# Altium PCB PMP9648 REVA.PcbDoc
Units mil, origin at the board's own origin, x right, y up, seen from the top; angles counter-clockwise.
Board outline 3200 x 1500 mil, 2 copper layers (Top Layer, Bottom Layer), stack 64.8 mil thick; 58 components, 29 nets, 134 pads, 77 vias.
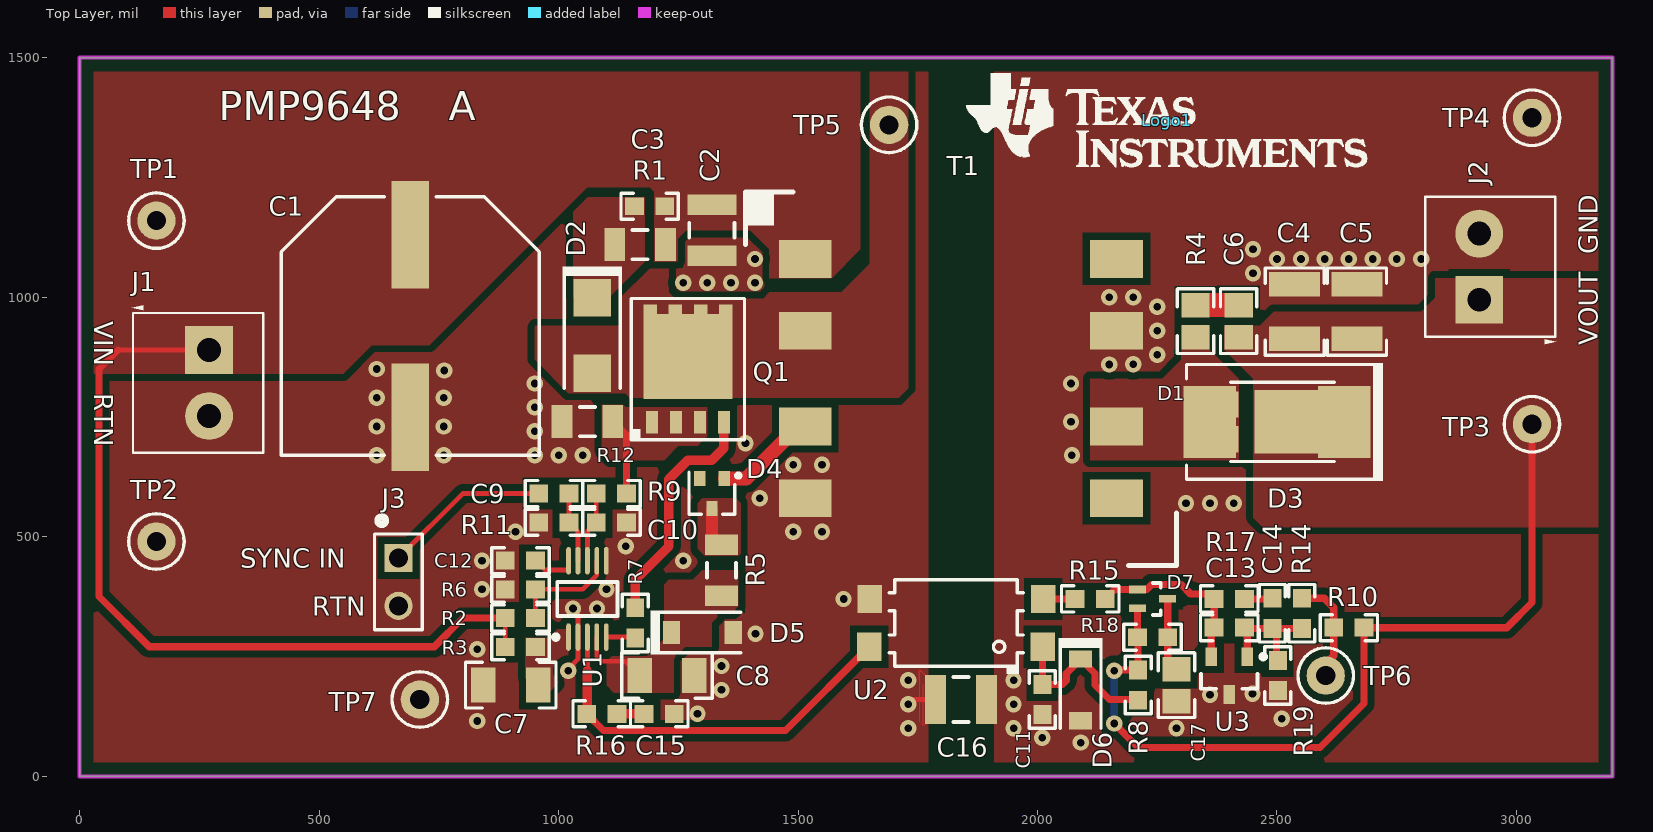
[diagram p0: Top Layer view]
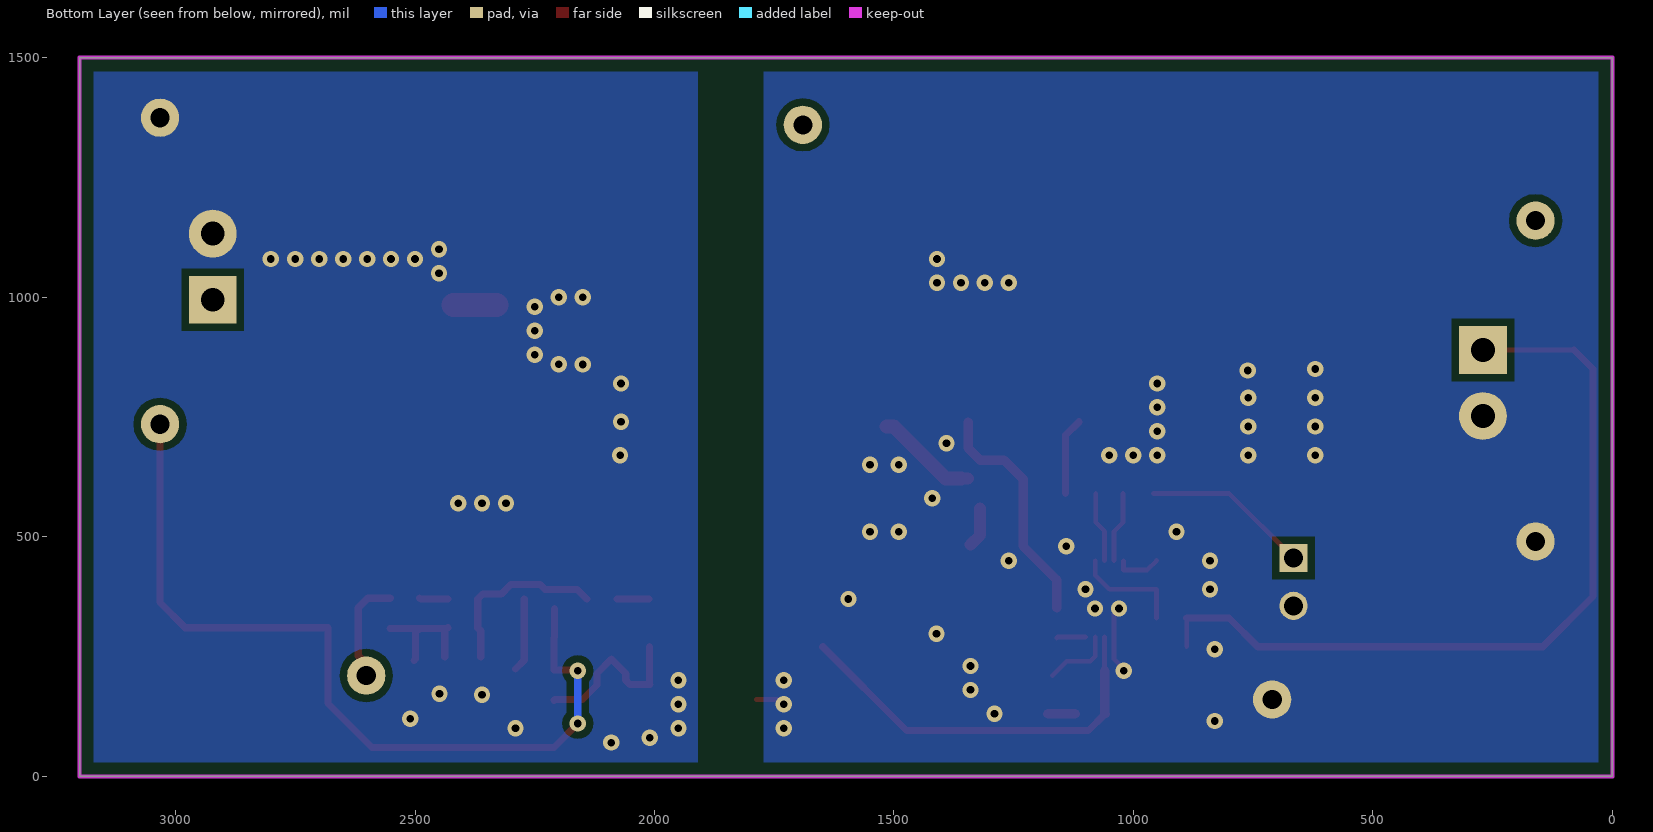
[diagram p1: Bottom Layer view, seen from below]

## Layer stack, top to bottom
Top Solder: solder mask 0.4, Solder Resist, Dk 3.5
Top Layer: signal copper 2.8
Dielectric1: core 59.2, FR-4, Dk 4.8
Bottom Layer: signal copper 2.8
Bottom Solder: solder mask 0.4, Solder Resist, Dk 3.5

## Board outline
0,0 3200,0 3200,1500 0,1500

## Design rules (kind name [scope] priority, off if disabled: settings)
AcuteAngle [All] p1: minimum=4.50000000000000E+0001 checktracksonly=FALSE
AssemblyTestPointUsage [All] p1: valid=2
Clearance Clearance_BoardEdge_MountingHoles [OnCopper and InComponentClass('Mounting Holes') vs IsKeepOut] p1: gap=25
Clearance Clearance_BoardEdge_Poly [OnCopper and InPoly vs IsKeepOut] p2: gap=25
Clearance Clearance_BoardEdge [OnCopper and Not InComponentClass('Logo') and not InComponentClass('FiducialMark') and not InRegion(1000,500,4000,800) and Not IsKeepout vs IsKeepOut] p3: gap=25
Clearance Clearance_Poly [InPolygon] p4: gap=15
Clearance [All] p5: gap=8
ComponentClearance ComponentClearance_Shunt [InComponentClass('Header') vs InComponentClass('Shunt')] p1: gap=0 collisioncheckmode=3 verticalgap=0 showdistances=FALSE
ComponentClearance ComponentClearance_Logo [InComponentClass('Logo')] p2: gap=50 collisioncheckmode=3 verticalgap=10 showdistances=FALSE
ComponentClearance ComponentClearance_ScrewToNut [(HasFootprint('NY PMS 440 0025 PH')) vs (HasFootprint('Keystone_1902C'))] p3: gap=5 collisioncheckmode=3 verticalgap=10 showdistances=FALSE
ComponentClearance ComponentClearance_MountingHoles [InComponentClass('Mounting Holes')] p4: gap=250 collisioncheckmode=3 verticalgap=100000 showdistances=FALSE
ComponentClearance ComponentClearance_SmallPassives [HasFootprint('0201*') or HasFootprint('0402*') or HasFootprint('0508') or HasFootprint('0603*') or HasFootprint('0612') or HasFootprint('0805*') or HasFootprint('0815*') or HasFootprint('0830*') or HasFootprint('1206*') or HasFootprint('1210*') or HasFootprint('1808*') or HasFootprint('1812*') or HasFootprint('1825*') or HasFootprint('2010*') or HasFootprint('2220*') or HasFootprint('2225*') or HasFootprint('2512*') or HasFootprint('2728*') or HasFootprint('3518*') vs HasFootprint('0201*') or HasFootprint('0402*') or HasFootprint('0508') or HasFootprint('0603*') or HasFootprint('0612') or HasFootprint('0805*') or HasFootprint('0815*') or HasFootprint('0830*') or HasFootprint('1206*') or HasFootprint('1210*') or HasFootprint('1808*') or HasFootprint('1812*') or HasFootprint('1825*') or HasFootprint('2010*') or HasFootprint('2220*') or HasFootprint('2225*') or HasFootprint('2512*') or HasFootprint('2728*') or HasFootprint('3518*')] p5: gap=10 collisioncheckmode=3 verticalgap=10 showdistances=FALSE
ComponentClearance ComponentClearance_THtoSMT [IsThruComponent vs IsSMTComponent] p6: gap=20 collisioncheckmode=3 verticalgap=30 showdistances=FALSE
ComponentClearance ComponentClearance_THtoTH [IsThruComponent vs IsThruComponent] p7: gap=50 collisioncheckmode=3 verticalgap=30 showdistances=FALSE
ComponentClearance [All] p8: gap=15 collisioncheckmode=3 verticalgap=10 showdistances=FALSE
DiffPairsRouting [All] p1: maxlimit=100 minlimit=10 mostfreqgap=10 toplayer_minwidth=15 toplayer_maxwidth=15 toplayer_prefwidth=15 bottomlayer_minwidth=15 bottomlayer_maxwidth=15 bottomlayer_prefwidth=15 maxuncoupledlength=1000
FabricationTestPointUsage TestPointUsage [All] p1: valid=2 allowmultiple=FALSE
FabricationTestpoint Testpoint [All] p1: side=3 testpointundercomponent=TRUE minsize=40 maxsize=100 preferedsize=60 minholesize=0 maxholesize=40 preferedholesize=32 testpointgrid=1 allowsidetop=TRUE allowsidebottom=TRUE usegrid=TRUE gridtolerance=0.01
FanoutControl Fanout_LCC [IsLCC] p1: bgadir=Out bgaviamode=Centered fanoutstyle=Auto fanoutdirection=Alternating viagrid=1 // Fanout_LCC (Default Rule)
FanoutControl Fanout_BGA [IsBGA] p2: bgadir=Out bgaviamode=Centered fanoutstyle=Auto fanoutdirection=Alternating viagrid=1 // Fanout_BGA (Default Rule)
FanoutControl Fanout_Default [All] p4: bgadir=Out bgaviamode=Centered fanoutstyle=Auto fanoutdirection=Alternating viagrid=1 // Fanout_Default (Default Rule)
FanoutControl Fanout_Small [(CompPinCount < 5)] p5: bgadir=Out bgaviamode=Centered fanoutstyle=Auto fanoutdirection=OutThenIn viagrid=1 // Fanout_Small (Default Rule)
HoleSize [All] p1: absolutevalues=TRUE maxlimit=251 minlimit=8 maxpercent=80.000 minpercent=20.000
MinimumAnnularRing MinimumAnnularRing_ThermalPadVias [IsVia and InAnyComponent] p1: minimumring=5.91
MinimumAnnularRing [All] p2: minimumring=9
MinimumSolderMaskSliver MinimumSolderMaskSliver_Logo [InComponentClass('Logo') vs InComponentClass('Logo')] p1: minsoldermaskwidth=0.7
MinimumSolderMaskSliver [All] p2: minsoldermaskwidth=3.94
PlaneClearance [All] p1: clearance=10
PlaneConnect [All] p1: planeconnectstyle=Direct reliefexpansion=10 reliefentries=4 reliefconductorwidth=10 reliefairgap=10
PolygonConnect [All] p1: connectstyle=Direct reliefconductorwidth=10 reliefentries=4 polygonreliefangle="90 Angle" airgapwidth=10
RoutingVias ThermalPadVias [IsVia and InAnyComponent] p1: holewidth=7.87 width=19.68 viastyle="Through Hole" minholewidth=7.87 minwidth=19.68 maxholewidth=12.99 maxwidth=23.62
RoutingVias [All] p2: holewidth=16 width=34 viastyle="Through Hole" minholewidth=7.87 minwidth=26 maxholewidth=40 maxwidth=65
SMDToCorner [All] p1: distance=30000
SilkToSilkClearance [All] p1: silktosilkclearance=0
SilkToSolderMaskClearance SilkscreenOverComponentPads [IsPad] p1: minsilkscreentomaskgap=0 clearancetoexposedcopper=TRUE
SolderMaskExpansion [All] p1: expansion=1.97
Width [All] p1: maxlimit=100 minlimit=6 preferedwidth=10 checkconnectedcopper=TRUE
15 further rules are at their usual default settings.

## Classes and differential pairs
component class Logo: Logo1

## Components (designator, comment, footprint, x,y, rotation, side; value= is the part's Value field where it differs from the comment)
C1 "EEV-FK2A470Q" SM_RADIAL_H13 690,940 r270 top
C2 "C3225X7R2A225M230AB" 1210L 1320,1140 r270 top
C3 "GRM188R72A104KA35D" 0603 1190,1190 r180 top
C4 "C3225X7R1C226M250AC" 1210 2536.85,970 r90 top
C5 "C3225X7R1C226M250AC" 1210 2666.85,970 r90 top
C6 "GRM2165C2A331JA01D" 0805 2420,950 r90 top
C7 "C3216X7R2A105M160AA" 1206 900,190 r180 top
C8 "C3216X7R1C106M" 1206 1226.5,210 r0 top
C9 "C1608C0G1H101J" 0603 990,590 r0 top
C10 "C1608C0G1H101J" 0603 1110,530 r180 top
C11 "DNP" 0603 2010,160 r270 top
C12 "C1608X7R1H103K" 0603 920,450 r180 top
C13 "" 0603 2400.31,310 r0 top
C14 "C1608X7R2A472K" 0603 2490.31,340 r270 top
C15 "GRM188R72A104KA35D" 0603 1210,130 r180 top
C16 "C1210C102KGRACTU" 1210L 1840,160 r180 top
C17 "GRM21BR61E225KA12L" 0805 2290.31,190 r270 top
D1 "DNP" PowerDI5 2470,739.68 r0 top
D2 "MURA120T3G" SMA 1070,920 r270 top
D3 "B560C-13-F" SMC 2500,739.68 r180 top
D4 "BAV21WS-7-F" SOT-323 1320,590 r270 top
D5 "MMSZ4699T1G" SOD-123 1300,300 r0 top
D6 "DNP" SOD-123 2090,180 r270 top
D7 "BAT54ST-7-F" SOT-523 2240.31,370 r0 top
J1 "ED555/2DS" TERM_BLK_ED555-2DS 270,890 r270 top
J2 "ED555/2DS" TERM_BLK_ED555-2DS 2922.35,994.8 r90 top
J3 "PEC02SAAN" CONN_PEC02SAAN 665.47,405.47 r270 top
Logo1 "Texas Instruments" TI_Stacked_Overlay_Small 2270,1370 r0 top
Q1 "BSC12DN20NS3 G" PG-TDSON-8 1270,850 r90 top
R1 "CRCW120649K9FKEA" 1206L 1170,1110 r0 top
R2 "CRCW0603100KFKEA" 0603 920,330 r180 top
R3 "CRCW06033R24FKEA" 0603 920,270 r180 top
R4 "CRCW080522R1FKEA" 0805 2330,950 r90 top
R5 "CRCW120620R0JNEA" 1206L 1340,430 r270 top
R6 "CRCW06033K74FKEA" 0603 920,390 r0 top
R7 "MCR03EZPJ000" 0603 1160,320 r90 top
R8 "CRCW06034K64FKEA" 0603 2210,190 r270 top
R9 "CRCW0603221RFKEA" 0603 1110,590 r0 top
R10 "CRCW06030000Z0EA" 0603 2650,310 r0 top
R11 "CRCW060342K2FKEA" 0603 990,530 r0 top
R12 "RLP73K2BR16FTDF" 1206L 1060,740 r0 top
R14 "CRCW0603100KFKEA" 0603 2551.81,340 r90 top
R15 "CRCW06031K50FKEA" 0603 2110,370 r180 top
R16 "CRCW06031K15FKEA" 0603 1090,130 r180 top
R17 "CRCW0603100KFKEA" 0603 2400.31,370 r180 top
R18 "CRCW060310K0FKEA" 0603 2240.31,290 r180 top
R19 "CRCW060311K3FKEA" 0603 2501.81,210 r90 top
T1 "750314749" RENCO_RLTI-1102 1840,830 r270 top
TP1 "5000" Keystone5000 160,1160 r0 top
TP2 "5001" Keystone5001 160,490 r0 top
TP3 "5000" Keystone5000 3032.35,734.8 r0 top
TP4 "5001" Keystone5001 3032.35,1374.8 r0 top
TP5 "5000" Keystone5000 1690,1360 r0 top
TP6 "5000" Keystone5000 2601.81,210 r0 top
TP7 "5001" Keystone5001 710,160 r0 top
U1 "LM5022MM" MUB10A_L 1060,370 r90 top
U2 "FOD817AS" N04C 1830,320 r180 top
U3 "LMV431AIMFX/NOPB" MF03A_L 2400.31,210 r270 top

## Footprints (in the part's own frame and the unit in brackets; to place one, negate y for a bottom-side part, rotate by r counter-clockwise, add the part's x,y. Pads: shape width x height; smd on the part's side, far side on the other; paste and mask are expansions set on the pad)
0603 [mm] "0603 from SM-752 data"
  rect 1x0.95 smd: 1(-0.8,0) 2(0.8,0)
  silkscreen extent -1.52,-0.69 1.52,0.69, body extent -0.87,-0.47 0.87,0.47, height 0.85
0805 [mm] "0805 from SM-752 data"
  rect 1.3x1.5 smd: 1(-0.85,0) 2(0.85,0)
  silkscreen extent -1.72,-0.97 1.72,0.97, body extent -1.1,-0.72 1.1,0.72, height 1.1
1206 [mm] "1206 from SM-752 data"
  rect 1.3x1.85 smd: 1(-1.45,0) 2(1.45,0)
  silkscreen extent -2.4,-1.21 2.4,1.21, body extent -1.7,-0.9 1.7,0.9, height 1.35
1206L [mm] "1206 from SM-752 data"
  rect 1.1x1.75 smd: 1(-1.35,0) 2(1.35,0)
  silkscreen extent -0.4,-0.77 0.4,0.77, body extent -1.7,-0.9 1.7,0.9, height 1.35
1210 [mm] "1210 from SM-752 data"
  rect 1.3x2.7 smd: 1(-1.45,0) 2(1.45,0)
  silkscreen extent -2.32,-1.57 2.32,1.57, body extent -1.7,-1.35 1.7,1.35, height 1.35
1210L [mm] "1210 from SM-752 data"
  rect 1.1x2.6 smd: 1(-1.35,0) 2(1.35,0)
  silkscreen extent -0.4,-1.2 0.4,1.2, body extent -1.7,-1.35 1.7,1.35, height 1.35
CONN_PEC02SAAN [mm] "SULLINS"
  rect 1.5x1.5 hole 1.016: 1(-1.27,0)
  round 1.5 hole 1.016: 2(1.27,0)
  silkscreen extent -3.45,-1.27 2.54,1.27, body extent -2.54,-1.27 2.54,1.27, height 8.38
Keystone5000 [mil] "For Keystone 500x miniature loop terminals"
  round 80 hole 40: 1(0,0)
  silkscreen extent -58,-58 58,58, body extent -49,-49 49,49, height 182
Keystone5001 [mil] "For Keystone 500x miniature loop terminals"
  round 80 hole 40: 1(0,0)
  silkscreen extent -58,-58 58,58, body extent -49,-49 49,49, height 182
MF03A_L [mm] "SOT23, 3-Leads, Body 2.9x1.3mm, Pitch 0.95mm, Lead Span 2.4mm, IPC High Density"
  rect 1x0.6 smd: 1(-1,0.95) 2(-1,-0.95) 3(1,0)
  silkscreen extent -1.12,-1.5 0.7,1.93, body extent -0.7,-1.5 0.7,1.5, height 1.12
MUB10A_L [mm] "TSSOP, 10-Leads, Body 3x3mm, Pitch 0.5mm, IPC High Density"
  oval 1.45x0.25 smd: 1(-2.025,1) 2(-2.025,0.5) 3(-2.025,0) 4(-2.025,-0.5) 5(-2.025,-1) 6(2.025,-1) 7(2.025,-0.5) 8(2.025,0) 9(2.025,0.5) 10(2.025,1)
  silkscreen extent -2.15,-1.6 0.9,1.8, body extent -1.6,-1.6 1.6,1.6, height 1.09
N04C [mm] "FAIRCHILD"
  rect 1.3x1.5 smd mask+0.065: 1(-4.587,1.27) 2(-4.612,-1.27) 3(4.588,-1.27) 4(4.613,1.27)
  silkscreen extent -3.56,-2.3 3.56,2.72, body extent -5.08,-2.3 5.08,2.3, height 3.87
PG-TDSON-8 [mm] "Infineon recommended land pattern"
  rect 1.2x0.65 smd: 1(-2.825,1.905) 2(-2.825,0.635) 3(-2.825,-0.635) 4(-2.825,-1.905)
  rect 0.5x0.7 smd: 5(3.175,-2) 6(3.175,-0.675) 7(3.175,0.675) 8(3.175,2)
  rect 4.5x4.7 smd paste-2.25: 9(0.675,0)
  silkscreen extent -3.74,-3 3.74,3, body extent -3.17,-2.89 3.17,2.9, height 1.1
PowerDI5 [mm] "Diodes Inc recommended land pattern, ap02001.pdf rev 60"
  rect 1.4x1.39 smd: 1(-1.991,0.92) 2(-1.991,-0.92)
  rect 4.86x3.36 smd: 3(1.991,0)
  silkscreen extent -1.7,-2.1 3.8,2.1, body extent -2.27,-2.03 4.33,2.03, height 1.17
RENCO_RLTI-1102 [mm] "RENCO"
  rect 2x2.8 smd: 1(-6.35,-8.255) 2(-2.54,-8.255) 3(2.54,-8.255) 4(6.35,-8.255) 5(6.35,8.255) 6(2.54,8.255) 7(-2.54,8.255) 8(-6.35,8.255)
  silkscreen extent -9.91,-11.43 9.91,11.43, body extent -9.65,-11.18 9.65,11.18, height 12.98
SM_RADIAL_H13 [mm] "12.5 x 13.5mm:  Panasonic H13"
  rect 5.7x2 smd: 1(-4.85,0) 2(4.85,0)
  silkscreen extent -6.85,-6.85 6.85,6.85, body extent -6.85,-6.85 6.85,6.85, height 14
SMA [mm] "Molded Diode, 2-Leads, Body 4.3x2.6mm, IPC Medium Density, based on OnSemi component dimensions and land pattern"
  rect 2x2 smd: 1(-2,0) 2(2,0)
  silkscreen extent -3.66,-1.57 2.79,1.57, body extent -2.6,-1.3 2.6,1.3, height 2.42
SMC [mil] "Molded Diode, 2-Leads, Body 6.9x5.8mm, IPC Medium Density, based on OnSemi component dimensions and land patterns"
  rect 110x150 smd: 1(-140.49,0) 2(140.49,0)
  silkscreen extent -221,-124 189,123, body extent -156,-116 156,116, height 91
SOD-123 [mm] "On Semi recommended land pattern"
  rect 0.915x1.22 smd: 1(-1.637,0) 2(1.637,0)
  silkscreen extent -2.74,-1.17 2.03,1.17, body extent -1.93,-0.9 1.93,0.9, height 1.35
SOT-323 [mm] "Zetex recommended land pattern.  March 2007"
  rect 0.8x0.6 smd: 1(-0.8,0.65) 2(-0.8,-0.65) 3(0.8,0)
  silkscreen extent -1.14,-1.22 1.09,1.49, body extent -1.13,-1.13 1.12,1.12, height 1.13
SOT-523 [mm] "From Diodes Inc datasheet component parameters"
  rect 0.9x0.4 smd: 1(-0.8,0.5) 2(-0.8,-0.5) 3(0.8,0)
  silkscreen extent 0.02,-0.85 0.42,0.85, body extent -0.8,-0.8 0.8,0.8, height 0.79
TERM_BLK_ED555-2DS [mil]
  rect 100x100 hole 50: 1(0,0)
  round 100 hole 50: 2(138,0)
  silkscreen extent -93,-161 215,113, body extent -69,-150 207,106, height 323
TI_Stacked_Overlay_Small [mil]
  silkscreen extent -418,-98 418,98

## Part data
C1: "CAP, AL, 47uF, 100V, +/-20%, 0.32 ohm, SMD"
C2: library part C3225X7R1C226M, "CAP, CERM, 2.2uF, 100V, +/-20%, X7R, 1210"
C3 C15: "CAP, CERM, 0.1uF, 100V, +/-10%, X7R, 0603"
C4 C5: library part C3225X7R1C226M, "CAP, CERM, 22uF, 16V, +/-20%, X7R, 1210"
C6: "CAP, CERM, 330 pF, 100 V, +/- 5%, C0G/NP0, 0805"
C7: "CAP, CERM, 1uF, 100V, +/-20%, X7R, 1206"
C8: "CAP, CERM, 10uF, 16V, +/-20%, X7R, 1206"
C9 C10: "CAP, CERM, 100pF, 50V, +/-5%, C0G/NP0, 0603"
C11: library part GRM188R72A104KA35D, "CAP, CERM, 0.1uF, 100V, +/-10%, X7R, 0603"
C12: "CAP, CERM, 0.01uF, 50V, +/-10%, X7R, 0603"
C13: library part C1608C0G1H470J, "CAP, CERM, open, 0603"
C14: "CAP, CERM, 4700pF, 100V, +/-10%, X7R, 0603"
C16: "CAP, CERM, 1000pF, 2000V, +/-10%, X7R, 1210"
C17: "CAP, CERM, 2.2 µF, 25 V, +/- 10%, X5R, 0805"
D1: library part PDS340, "Diode, Schottky, PowerDI5"
D2: "Diode, Ultrafast, 200V, 1A, SMA"
D3: "Diode, Schottky, 60 V, 5 A, SMC"
D4: "Diode, Switching, 200 V, 0.2 A, AEC-Q101, SOD-323"
D5: "Diode, Zener, 12 V, 500 mW, SOD-123"
D6: library part MMSZ5236B-7-F, "Diode, Zener, 7.5V, 500mW, SOD-123"
D7: "Diode, Schottky, 30V, 0.2A, SOT-523"
J1 J2: "Terminal Block, 6A, 3.5mm Pitch, 2-Pos, TH"
J3: "Header, 100mil, 2x1, Tin plated, TH"
Logo1: library part TI_Logo, "Texas Instrument Corporate Signature"
Q1: "MOSFET, N-CH, 200 V, 11.3 A, PG-TDSON-8"
R1: "RES, 49.9k ohm, 1%, 0.25W, 1206"
R2 R14 R17: "RES, 100k ohm, 1%, 0.1W, 0603"
R3: "RES, 3.24, 1%, 0.1 W, 0603"
R4: "RES, 22.1, 1%, 0.125 W, 0805"
R5: "RES, 20 ohm, 5%, 0.25W, 1206"
R6: "RES, 3.74k ohm, 1%, 0.1W, 0603"
R7 R10: "RES, 0 ohm, 5%, 0.1W, 0603"
R8: "RES, 4.64 k, 1%, 0.1 W, 0603"
R9: "RES, 221 ohm, 1%, 0.1W, 0603"
R11: "RES, 42.2 k, 1%, 0.1 W, 0603"
R12: "RES, 0.16, 1%, 0.5 W, 1206"
R15: "RES, 1.50k ohm, 1%, 0.1W, 0603"
R16: "RES, 1.15 k, 1%, 0.1 W, 0603"
R18: "RES, 10.0k ohm, 1%, 0.1W, 0603"
R19: "RES, 11.3 k, 1%, 0.1 W, 0603"
T1: "Transformer, 82uH, 1:0.4:0.33, 2.7A, SMT"
TP1 TP3 TP5 TP6: "Test Point, TH, Miniature, Red"
TP2 TP4 TP7: "Test Point, TH, Miniature, Black"
U1: "60V Low Side Controller for Boost and SEPIC, 10-pin MSOP"
U2: library part FOD817DS, "Optocoupler, 5kV RMS, 80% - 160%, SMT"
U3: "Low-Voltage (1.24V) Adjustable Precision Shunt Regulators, 3-pin SOT-23, Pb-Free"

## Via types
v1: diameter 34, hole 16, Top Layer to Bottom Layer, 77 vias

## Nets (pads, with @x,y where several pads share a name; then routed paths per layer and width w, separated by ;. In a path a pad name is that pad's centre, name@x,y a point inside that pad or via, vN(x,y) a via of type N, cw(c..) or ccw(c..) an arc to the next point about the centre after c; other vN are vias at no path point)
GND2: C4.2 C5.2 C11.2 C16.1 C17.2 D6.2 J2.2 R19.1 T1.7 TP4.1 U3.3
  other v1: 2090,70 2010,80 1950,100 2290,100 2510,120 1950,150 2360,170 2449,172 1950,200 2310,570 2360,570 2410,570 2071.76,670 2070,740 2070,820 2150,859.53 2200,860 2250,880 2250,930 2250,980 2150,1000 2200,1000 2450,1050 2500,1080 2550,1080 2600,1080 2650,1080 2700,1080 2750,1080 2801.35,1080 2450,1100
NetC1_1: C1.1 C2.1 C3.1 J1.1 R1.2 R2.2 R3.2 T1.1 TP1.1 | length 1698.4
  Top Layer w10: 80,890 J1.1 ; R3.2 R2.2
  Top Layer w15: 80,890 40,850 40,375 145,270 740,270 800,330 R2.2
NetC3_2: C3.2 D2.1 R1.1
NetC4_1: C4.1 C5.1 C6.1 D1.3 D3.1 D7.2 J2.1 R8.1 R10.2 R18.2 TP3.1 | length 1773.5
  Top Layer w10: R18.2 R18.2@2210,288.82
  Top Layer w15: v1(2160,110) 2210,60 2590,60 2681.5,151.5 R10.2 2980,310 3032.35,362.35 TP3.1 ; v1(2160,220) 2161.5,221.5 R8.1 R18.2@2210,288.82 ; R18.2 D7.2
  Bottom Layer w15: v1(2160,110) v1(2160,220)
NetC6_2: C6.2 R4.2 | length 90
  Top Layer w50: R4.2 C6.2
NetC7_1: C7.1 R3.1 U1.1
NetC8_1: C8.1 D5.1 R5.2 U1.4 | length 146.4
  Top Layer w10: U1.4 1079.68,250.32 1090,240 1139.41,240 C8.1
NetC9_1: C9.1 J3.1 | length 348.8
  Top Layer w10: J3.1 800,590 C9.1
NetC9_2: C9.2 R11.2 U1.9 | length 148.1
  Top Layer w10: C9.2 R11.2 1040.31,511.18 U1.9
NetC10_2: C10.2 R9.1 U1.8 | length 147.9
  Top Layer w10: U1.8 1060,511.5 C10.2 R9.1
NetC11_1: C11.1 D6.1 R8.2 U2.1 | length 359.1
  Top Layer w15: U2.1 2010.61,192.11 C11.1 2051.5,191.5 2060,200 2060,214.47 D6.1 2120,214.47 2120,190 2150,160 2208.5,160 R8.2
NetC12_1: C12.1 U1.10 | length 96.3
  Top Layer w10: C12.1 970.87,430.63 1020.63,430.63 U1.10
NetC13_1: C13.1 D7.1 R15.1 R17.2 U3.2 | length 375.3
  Top Layer w15: R15.1 2161.18,389.68 D7.1 2228.19,389.68 2238.5,400 2300,400 2320,380 2358.82,380 R17.2 C13.1 2362.91,304.09 U3.2
NetC13_2: C13.2 C14.2 R14.1 R19.2 U3.1 | length 253.3
  Top Layer w15: C13.2 C13.2@2433.31,308.5 ; U3.1 2437.72,304.09 C13.2@2433.31,308.5 ; R19.2 2498.82,244.49 2498.82,300 C14.2 ; R14.1 C14.2 ; C13.2@2433.31,308.5 C14.2
NetC14_1: C14.1 R17.1 | length 59.1
  Top Layer w15: R17.1 2488.82,370 C14.1
NetC15_2: C15.2 R16.1 | length 57
  Top Layer w20: R16.1 C15.2
NetC17_1: C17.1 D7.3 R18.1 | length 154.2
  Top Layer w15: D7.3 R18.1 2271.81,241.97 C17.1
NetD1_1: D1.1 D1.2 D3.2 R4.1 T1.6
NetD2_2: D2.2 Q1.5 Q1.6 Q1.7 Q1.8 Q1.9 T1.2 TP5.1
NetD4_1: D4.1 T1.3 | length 214.4
  Top Layer w25: D4.1 1359.37,621.5
  Top Layer w30: 1359.37,621.5 1391.5,621.5 1500,730 T1.3
NetD4_3: D4.3 R5.1 | length 83.6
  Top Layer w25: D4.3 1320,503.15 R5.1
NetQ1_1: Q1.1 Q1.2 Q1.3 R9.2 R12.2 | length 161.7
  Top Layer w15: R12.2 1141.5,711.65 R9.2
NetQ1_4: Q1.4 R7.2 | length 493.2
  Top Layer w20: R7.2 1160,410 1230,480 1230,620 1270,660 1320,660 1345,685 Q1.4
NetR2_1: R2.1 R6.2 U1.7 | length 230.5
  Top Layer w10: R2.1 R6.2 1050,390 1079.68,419.68 U1.7
NetR7_1: R7.1 U1.5 | length 61.4
  Top Layer w10: U1.5 1158.23,290.28 R7.1
NetR10_1: R10.1 R14.2 TP6.1 | length 223.4
  Top Layer w15: R14.2 2598.5,371.5 2618.5,351.5 R10.1 2618.5,251.5 2601.81,234.8 TP6.1
NetR15_2: R15.2 U2.2 | length 66.9
  Top Layer w15: U2.2 R15.2
NetR16_2: R16.2 U1.3 U2.4 | length 837.8
  Top Layer w10: 1060,220 U1.3
  Top Layer w15: R16.2 1093.5,95 1473.41,95 U2.4
  Top Layer w20: R16.2 1060,131.5 1060,220
RTN: C1.2 C2.2 C7.2 C8.2 C10.1 C12.2 C15.1 C16.2 D5.2 J1.2 J3.2 R6.1 R11.1 R12.1 T1.4 TP2.1 TP7.1 U1.2 U1.6 U2.3 | length 203.7
  Top Layer w10: v1(1020,220) 1020,223.77 1040.31,244.08 U1.2 1040.31,339.69 v1(1030,350) ; v1(1730,150) 1740,160 C16.2
  other v1: 1730,100 830,115 1290,130 1340,180 1730,200 1340,230 830,265 1411,297 1080,350 1595,370 840,390 1100,390 840,450 1260,450 1140,480 910,510 1490,510 1550,510 1420,580 1490,650 1550,650 620,670.32 760,670.32 950,670 1000,670 1050,670 1390,695 950,720 620,730 760,730 950,770 620,790 760,790 950,820 761,847 620,850 1260,1030 1310,1030 1360,1030 1410,1030 1410,1080
pads on no net: D4.2 T1.5 T1.8

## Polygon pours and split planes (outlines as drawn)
NetC1_1 on Top Layer "Top Layer-No Net" (solid, pour order 2): 0,1500 -2.5,1497.5 -2.5,840 550,840 600,890 610,900 730,900 840,1010 1040,1210 1060,1230 1190,1230 1200,1220 1200,1074.57 1245.79,1074.57 1248.74,1071.61 1248.74,1120 1248.74,1121.89 1266.85,1140 1373.13,1140 1400,1140 1440,1100 1440,1040 1570,1040 1630,1100 1630,1290 1630,1500
NetC3_2 on Top Layer "Top Layer-No Net 1" (solid, pour order 6): 1030,1000 1030,1040 1030,1180 1060,1210 1061.3,1208.7 1180,1208.7 1180,1074.57 1105.43,1000 1100,1000
NetD2_2 on Top Layer "Top Layer-No Net 2" (solid, pour order 8): 1030,940 1128.5,940 1128.5,973.85 1151.89,997.24 1360,997.24 1427.24,997.24 1440,1010 1590,1010 1650,1070 1650,1500 1730,1500 1730,1290 1730,810 1710,790 1420,790 1148.82,790 1138.9,799.92 1050,799.92 1020.08,799.92 950,870 959.68,879.68 959.68,940
NetD2_2 on Top Layer "Top Layer-No Net 3" (solid, pour order 10): 950,870 950,936.29 946.29,940 1128.5,940 1128.5,998.5 1190,1060 1230,1060 1230,1010 1252.68,987.32 1252.68,969.09 1252.68,872.68 1250,870
NetD4_3 on Top Layer "Top Layer-No Net 7" (solid, pour order 18): 1304.57,460 1290,474.57 1290,500 1290,570 1300,580 1370,580 1380,570 1380,490 1380,464.57 1375.43,460
NetQ1_1 on Top Layer "Top Layer-No Net 8" (solid, pour order 20): 1090,775.43 1134.57,775.43 1140,770 1160,770 1310,770 1310,710 1300,700 1290,690 1260,690 1250,690 1220,660 1110,660 1107.99,660 1090,677.99
NetC8_1 on Top Layer "Top Layer-No Net 5" (solid, pour order 24): 1375.43,429.98 1299.98,429.98 1280,410 1230,410 1220,400 1220,284 1217.11,284 1183.43,250.32 1110.78,250.32 1110.32,250.32 1100,240 1100,190 1115.43,174.57 1240,174.57 1240,245.43 1264.57,270 1270,270 1320,270 1320,320 1342.5,342.5 1363.72,342.5 1375.43,354.21
NetD1_1 on Top Layer "Top Layer-No Net 4" (solid, pour order 26): 2110,830 2110,660 2420,660 2420,819.41 2420,829.61 2380,869.61 2360,889.61 2360,890 2360,938.54 2358.54,940 2301.46,940 2301.46,891.46 2300,890 2300,869.61 2299.61,869.61 2260,830
NetC4_1 on Top Layer "Top Layer-No Net 6" (solid, pour order 28): 2391.46,940 2390,938.54 2390,890 2450,830 2450,670 2450,540 2470,520 3200,520 3200,1037.5 3202.5,1040 2830,1040 2830,998.65 2801.35,970 2536.85,970 2493.7,970 2483.7,960 2463.7,940 2450,940 2448.54,940
NetC7_1 on Top Layer "Top Layer-No Net 10" (solid, pour order 36): 930,203.86 930,288.7 978.7,288.7 997.01,307.01 1020,307.01 1020,220 1005,220 1005,200 980,175
RTN on Top Layer "Top Layer-No Net 11" (solid, pour order 40): -2.5,0 1772,0 1772,1500 1769.49,1502.5 0.01,1502.5
RTN on Top Layer "Top Layer-No Net 9" (solid, pour order 48): 1777,118 1774.38,118 1761.26,104.88 1754,112.14 1754,219 1757,219 1769,207 1778,198 1778,180
RTN on Top Layer "Top Layer-No Net 12" (solid, pour order 50): 1769,111 1767.38,111 1761.26,104.88 1761.26,190.74 1752,200 1753,201 1753,222 1754,222 1772,204
GND2 on Top Layer "Top Layer-No Net 13" (solid, pour order 54): 1910,0 1910,1500 3200,1500 3200,0
RTN on Bottom Layer "Bottom Layer-No Net" (solid, pour order 42): 0.01,-2.5 1769.49,-2.5 1772,0 1772,1500 -2.5,1500
GND2 on Bottom Layer "Bottom Layer-No Net 1" (solid, pour order 52): 1910,0 1910,1500 3200,1500 3200,0

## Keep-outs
Keep-Out Layer:
  lines w5: -2.5,0 ccw(c0,0) 0,-2.5 ; -2.5,0 ccw(c0,0) 0,-2.5 ; -2.5,0 -2.5,1500 ; -2.5,1500 cw(c0,1500) 0,1502.5 ; -2.5,1500 cw(c0,1500) 0,1502.5 ; 0,-2.5 3200,-2.5 ; 0,1502.5 3200,1502.5 ; 3200,-2.5 ccw(c3200,0) 3202.5,0 ; 3200,-2.5 ccw(c3200,0) 3202.5,0 ; 3200,1502.5 cw(c3200,1500) 3202.5,1500 ; 3200,1502.5 cw(c3200,1500) 3202.5,1500 ; 3202.5,0 3202.5,1500
  lines w7: 0,0 3200,0 3200,1500 0,1500 0,0
  text ".Layer_Name" at 577,-858.49 h60

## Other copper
Top Layer:
  text ".Layer_Name" at 577,-858.49 h60
Bottom Layer:
  text ".Layer_Name" at 577,-858.49 h60

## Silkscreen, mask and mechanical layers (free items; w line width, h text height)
Top Overlay:
  text "PMP9648" at 290,1370 h60
  text "A" at 770,1370 h60
  text "GND" at 3170,1090 h40 r90
  text "VIN" at 30,950 h40 r270
  text "VOUT" at 3170,900 h40 r90
  text "RTN" at 30,800 h40 r270
  text "SYNC IN" at 335,435 h40
  text "RTN" at 485,335 h40
  text ".Layer_Name" at 577,-858.49 h60
Bottom Overlay:
  text ".Layer_Name" at 577,-858.49 h60
Top Paste:
  text ".Layer_Name" at 577,-858.49 h60
Bottom Paste:
  text ".Layer_Name" at 577,-858.49 h60
Top Solder:
  text ".Layer_Name" at 577,-858.49 h60
  text ".Layer_Name" at 577,-858.49 h60
Bottom Solder:
  text ".Layer_Name" at 577,-858.49 h60
Drill Guide:
  text ".Layer_Name" at 577,-858.49 h60
M1 Board Outline:
  the board outline again, w7
  text ".Layer_Name" at 577,-858.49 h60
M2 Board Dimensions:
  rectangle: 124.5,-410.5 499.5,-285.5
  rectangle: -0.5,-285.5 124.5,-160.5
  lines w7: -0.5,-285.5 999.5,-285.5 ; 124.5,-410.5 124.5,-160.5 ; 249.5,-410.5 249.5,-160.5 ; 499.5,-410.5 499.5,-160.5 ; 749.5,-410.5 749.5,-160.5 ; -0.5,-410.5 -0.5,-160.5 999.5,-160.5 999.5,-410.5 -0.5,-410.5
  lines w10: -0.5,-475.5 -0.5,-455.5 ; 59.5,-485.5 -0.5,-465.5 ; 59.5,-445.5 -0.5,-465.5 ; 223.58,-465.5 -0.5,-465.5 ; 775.42,-465.5 999.5,-465.5 ; 939.5,-485.5 999.5,-465.5 ; 939.5,-445.5 999.5,-465.5 ; 999.5,-475.5 999.5,-455.5
  text "1000 (mil)" at 233.58,-501.49 h60
  text ".Layer_Name" at 577,-858.49 h60
M3 3D STEP Top:
  text ".Layer_Name" at 577,-858.49 h60
M4 3D STEP Bottom:
  text ".Layer_Name" at 577,-858.49 h60
M5 Assembly Top:
  lines w10: -292,-930.17 6308,-930.17 ; -292,-726.83 6310,-726.83 ; -292,-523.5 -292,-1133.5 3713,-1133.5 6310,-1133.5 6310,-523.5 -291.5,-523.5 -291.5,-1133.5 1284,-1133.5 ; 2173,-1133.5 2173,-523.5 ; 3440,-726.83 3440,-523.5 ; 4280,-726.83 4280,-523.5 ; 4902,-1140 4902,-937.17
  text "COMPONENTS MARKED 'DNP' SHOULD NOT BE POPULATED." at 1153.5,-318.5 h60
  text "ASSEMBLY VARIANT:" at 1153,-434 h60
  text ".VariantName" at 2189,-434 h60
  text "PCB VIEWED FROM TOP SIDE" at -228.5,-655.67 h60
  text "BOARD #:" at 2248,-655.67 h60
  text "PMP9648" at 2793.5,-655.67 h60
  text "REV:" at 3638,-655.67 h60
  text "A" at 3929.5,-655.67 h60
  text "SVN REV:" at 4476,-655.67 h60
  text ".VersionControl_RevNumber" at 4982,-655.67 h60
  text "IGNORE ->" at -228.5,-858.49 h60
  text "PLOT NAME =" at -228.5,-1064.34 h60
  text ".plot_File_Name" at 577,-1064.34 h60
  text "GENERATED    :" at 2250,-1064.34 h60
  text ".Print_Date" at 3119.5,-1064.34 h60
  text ".Print_Time" at 3848.5,-1064.34 h60
  text "TEXAS INSTRUMENTS" at 5113,-1064.34 h60
M6 Assembly Bottom:
  lines w10: -292.5,-727.33 6309.5,-727.33 ; -290.5,-930.67 6309.5,-930.67 ; 1115.5,-1140.5 1115.5,-937.67 ; 1737.5,-727.33 1737.5,-524 ; 2577.5,-727.33 2577.5,-524 ; 3844.5,-1134 3844.5,-524 ; 4733.5,-1134 6309,-1134 6309,-524 -292.5,-524 -292.5,-1134 2304.5,-1134 6309.5,-1134 6309.5,-524
  text "COMPONENTS MARKED 'DNP' SHOULD NOT BE POPULATED." at 6102,-318 h60
  text ".VariantName" at 5058,-434 h60
  text "ASSEMBLY VARIANT:" at 6097,-434 h60
  text ".VersionControl_RevNumber" at 1035.5,-656.17 h60
  text "SVN REV:" at 1541.5,-656.17 h60
  text "A" at 2088,-656.17 h60
  text "REV:" at 2379.5,-656.17 h60
  text "PMP9648" at 3224,-656.17 h60
  text "BOARD #:" at 3769.5,-656.17 h60
  text "PCB VIEWED FROM BOTTOM SIDE" at 6246,-656.17 h60
  text "IGNORE ->" at 2547.85,-858.49 h60
  text "TEXAS INSTRUMENTS" at 904.5,-1064.84 h60
  text ".Print_Time" at 2169,-1064.84 h60
  text ".Print_Date" at 2898,-1064.84 h60
  text "GENERATED    :" at 3767.5,-1064.84 h60
  text ".plot_File_Name" at 5440.5,-1064.84 h60
  text "PLOT NAME =" at 6246,-1064.84 h60
M9 Title Sheet:
  drawing of 57 lines, arcs and shapes, not listed
  text "1" at 739.84,8036.5 h70
  text "2" at 3235.5,8036.5 h70
  text "3" at 5724.84,8036.5 h70
  text "4" at 8231.51,8036.5 h70
  text "5" at 10730.5,8036.5 h70
  text "6" at 13235.5,8036.5 h70
  text "A" at -416.5,6893.5 h70
  text "A" at 14383.5,6893.5 h70
  text "B" at -416.5,4513.5 h70
  text "B" at 14383.5,4513.5 h70
  text "C" at -416.5,2138.5 h70
  text "C" at 14383.5,2138.5 h70
  text "PROJECT TITLE:" at 11343.5,277.5 h45
  text ".PRJ_Title" at 11393.5,144.17 h70
  text "DESIGNED FOR:" at 11343.5,-23.5 h45
  text ".PRJ_Customer" at 11393.5,-163.5 h70
  text "D" at -416.5,-231.5 h70
  text "D" at 14383.5,-231.5 h70
  text "FILE NAME:" at 11343.5,-323.5 h45
  text ".PCB_File_Name_No_Path" at 11393.5,-443.5 h70
  text "Texas Instruments (TI) and/or its licensors do not warrant the accuracy or completeness of this specification" at 6374,-605.34 h45
  text "ENGINEER:" at 11343.5,-613.5 h45
  text "LAYOUT BY:" at 12848.5,-613.5 h45
  text "or any information contained therein. TI and/or its licensors do not warrant that this design will meet" at 6329.01,-718 h45
  text ".PRJ_Engineer" at 11393.5,-768.49 h70
  text ".PCB_Layout" at 12899,-768.49 h70
  text "the specifications, will be suitable for your application or fit for any particular purpose, or will operate in" at 6329.01,-830.67 h45
  text ".Layer_Name" at 577,-858.49 h60
  text "ALTIUM DESIGNER VERSION:" at 12848.5,-923.5 h45
  text "an implementation. TI and/or its licensors do not warrant that the design is production worthy. You should" at 6329.01,-943.33 h45
  text "completely validate and test your design implementation to confirm the system functionality for your application." at 6374,-1056 h45
  text ".print_Scale" at 11393.5,-1056.83 h70
  text ".Application_BuildNumber" at 12899,-1056.83 h70
  text "1" at 739.84,-1263.5 h70
  text "2" at 3235.5,-1263.5 h70
  text "3" at 5724.84,-1263.5 h70
  text "4" at 8231.51,-1263.5 h70
  text "5" at 10730.5,-1263.5 h70
  text "6" at 13235.5,-1263.5 h70
M10 Fab Notes:
  drawing of 212 lines, arcs and shapes, not listed
  text "DESIGN INFORMATION" at 12381.02,6810 h60
  text "(REFER ALSO ARRAY/PANEL PROFILING INFORMATION)" at 12019.46,6648.29 h60
  text "BOARD SIZE" at 11333.46,6644 h60
  text "3200MIL" at 11795.78,6516.18 h60
  text "X" at 12301.46,6516.18 h60
  text "1500MIL" at 12532.78,6516.18 h60
  text "Number of Layers :" at 11736.46,6319 h60
  text "2" at 12831.27,6309 h60
  text "MIN. TRACK WIDTH:" at 11736.46,6180 h60
  text "8" at 12832.7,6180 h60
  text "MIL" at 12987.46,6180 h60
  text "MIN. CLEARANCE:" at 11736.46,6048 h60
  text "8" at 12832.7,6048 h60
  text "MIL" at 12987.46,6048 h60
  text "MIN. VIA PAD SIZE:" at 11736.46,5916 h60
  text "24" at 12802.71,5916 h60
  text "MIL" at 12987.46,5916 h60
  text "0.05mm (2MIL)" at 12431.46,5774.29 h60
  text "MINIMUM ANNULAR RING" at 11407.23,5770 h60
  text "EXTERNAL" at 13139.46,5770 h60
  text "PER" at 11607.23,5652 h60
  text "IPC-D-275 CLASS 2 LEVEL C" at 11827.23,5652 h60
  text "MIL, HOLES" at 13315.46,5539.71 h60
  text "+/-" at 12923,5539 h60
  text "+/-" at 13777,5539 h60
  text "REGISTRATION TOLERANCES:" at 11407.23,5534 h60
  text "METAL" at 12607,5534 h60
  text "5" at 13183.2,5534 h60
  text "3" at 14016.2,5534 h60
  text "MIL" at 14132.46,5534 h60
  text "MATERIAL:" at 11332.46,5324.54 h60
  text "FR-4 High Tg" at 12318.9,5184.21 h60
  text "FR-408" at 11753.46,5175.64 h60
  text "X" at 12165.46,5175.64 h60
  text "OTHER" at 13241.46,5175.64 h60
  text "62 MIL (1.6mm) +/-10%" at 12073.56,5012.92 h60
  text "THICKNESS:" at 11407.23,5008.64 h60
  text "X" at 11945.4,5008.64 h60
  text "OTHER" at 13358.46,5008.64 h60
  text "TOLERANCE:" at 11407.23,4850.64 h60
  text "X" at 12246.53,4850.64 h60
  text "ANSI IPC-6012 TYPE 3 CLASS 2" at 12433.48,4850.64 h60
  text "OTHER +/-" at 12433.46,4694.64 h60
  text "BOW & TWIST:" at 11407.23,4537.64 h60
  text "X" at 12246.53,4537.64 h60
  text "ANSI IPC-6012 TYPE 3 CLASS 2" at 12433.48,4537.64 h60
  text "OTHER +/-" at 12433.46,4379.13 h60
  text "COPPER THICKNESS (FINISHED):" at 11332.46,4243.64 h60
  text "1.4MIL (1oz)" at 12212.46,4090.92 h60
  text "2MIL (1.4oz)" at 12979.46,4090.92 h60
  text "2.8MIL (2oz)" at 13706.46,4090.92 h60
  text "X" at 13580,4090 h60
  text "OUTER:" at 11689.46,4086.64 h60
  text "1.4MIL (1oz)" at 12212.46,3933.92 h60
  text "2.8MIL (2oz)" at 12979.46,3933.92 h60
  text "N/A" at 13706,3934.29 h60
  text "INNER SIGNAL:" at 11400.38,3929.64 h60
  text "X" at 12850,3930 h60
  text "DRILLING:" at 11332.46,3790.64 h60
  text "REFERENCE:" at 11407.23,3673.64 h60
  text "X" at 12055.46,3673.64 h60
  text "AS SHOWN" at 12242.46,3673.64 h60
  text "X" at 12956.46,3673.64 h60
  text "NC_DRILL FILES" at 13093.46,3673.64 h60
  text "PTH MIN COPPER THICKNESS:" at 11407.23,3515.64 h60
  text "X" at 12757.46,3515.64 h60
  text "1MIL" at 12894.46,3515.64 h60
  text "OTHER" at 13391.46,3515.64 h60
  text "BOARD FINISH:" at 11332.46,3356.64 h60
  text "SILKSCREEN:" at 11487.68,3238.64 h60
  text "X" at 12436.46,3238.64 h60
  text "TOP" at 12562.46,3238.64 h60
  text "X" at 12946.46,3238.64 h60
  text "BOTTOM" at 13073.46,3238.64 h60
  text "SILKSCREEN COLOR:" at 11487.68,3071.64 h60
  text "X" at 12435.42,3071.64 h60
  text "WHITE" at 12562.46,3071.64 h60
  text "OTHER" at 13073.46,3071.64 h60
  text "SOLDER RESIST COLOR:" at 11487.68,2901.64 h60
  text "GREEN" at 12182.46,2742.44 h60
  text "BLUE" at 12773.46,2742.44 h60
  text "OTHER" at 13311.46,2742.44 h60
  text "X" at 12650,2740 h60
  text "IMMERSION GOLD (ENIG)" at 12393.46,2553.92 h60
  text "ENEPIG" at 13731,2550.64 h60
  text "SURFACE FINISH:" at 11332.46,2549.64 h60
  text "IMM. TIN/SILVER OR EQUIV" at 11662,2392.64 h60
  text "OTHER" at 13093.46,2392.64 h60
  text "X" at 11500,2390 h60
  text "ARRAY/PANEL:" at 11332.46,2213.64 h60
  text "CUT AND TRIM PER MECH LAYER 1" at 12393.46,2209.35 h60
  text "N.C. ROUTE" at 12393.46,2057.64 h60
  text "X" at 13072.46,2057.64 h60
  text "V. SCORE" at 13259.46,2057.64 h60
  text "CERTIFICATION:" at 11332.46,1920.64 h60
  text "MATERIALS AND WORKMANSHIP FOR ALL PCBS" at 12057.46,1920.64 h60
  text "TO MEET OR EXCEED THE REQUIREMENTS OF:" at 12057.46,1822.64 h60
  text "X" at 11683.96,1686.13 h60
  text "ANSI IPC-A-600F CLASS ->" at 11822.96,1686.13 h60
  text "X" at 13462.02,1686.13 h60
  text "2" at 13580.96,1686.14 h60
  text "1" at 13265.96,1684.64 h60
  text "3" at 13934.96,1684.64 h60
  text "X" at 11686.02,1526.64 h60
  text "UL 94V-0" at 11822.96,1526.64 h60
  text "X" at 12498.02,1526.64 h60
  text "RoHS" at 12634.96,1526.64 h60
  text "OTHER" at 13279.36,1526.64 h60
  text "PER ORDER" at 13676.42,1526.64 h60
  text "ADDITIONAL REQUIREMENTS:" at 11332.46,1385.64 h60
  text "MICROSECTION:" at 11407.23,1270.64 h60
  text "YES" at 12312.96,1270.64 h60
  text "REQUIRED" at 13174.46,1114.49 h60
  text "BARE BOARD ELEC. TEST:" at 11407.23,1111.64 h60
  text "NONE" at 12712.96,1111.64 h60
  text "X" at 13047.46,1111.64 h60
  text "PER ORDER" at 13766.46,1111.64 h60
  text "MANUFACTURER'S UL:" at 11407.23,954.64 h60
  text "RAIL" at 12572.96,950.35 h60
  text "METAL" at 13064.77,950.35 h60
  text "X" at 13440,950 h60
  text "SILK" at 13576.46,950.35 h60
  text ".Layer_Name" at 577,-858.49 h60
M11 Gerber Information:
  lines w10: -292,-930.17 6308,-930.17 ; -292,-726.83 6310,-726.83 ; -292,-523.5 -292,-1133.5 3713,-1133.5 6310,-1133.5 6310,-523.5 -291.5,-523.5 -291.5,-1133.5 1284,-1133.5 ; 2173,-1133.5 2173,-523.5 ; 3440,-726.83 3440,-523.5 ; 4280,-726.83 4280,-523.5 ; 4902,-1140 4902,-937.17
  text "ALL ARTWORK VIEWED FROM TOP SIDE" at -228.5,-655.67 h60
  text "BOARD #:" at 2248,-655.67 h60
  text "PMP9648" at 2793.5,-655.67 h60
  text "REV:" at 3638,-655.67 h60
  text "A" at 3929.5,-655.67 h60
  text "SVN REV:" at 4476,-655.67 h60
  text ".VersionControl_RevNumber" at 4982,-655.67 h60
  text "LAYER NAME =" at -228.5,-858.49 h60
  text "PLOT NAME =" at -228.5,-1064.34 h60
  text ".plot_File_Name" at 577,-1064.34 h60
  text "GENERATED    :" at 2250,-1064.34 h60
  text ".Print_Date" at 3119.5,-1064.34 h60
  text ".Print_Time" at 3848.5,-1064.34 h60
  text "TEXAS INSTRUMENTS" at 5113,-1064.34 h60
M12 Stackup:
  lines w7: 11360,7610.17 14210,7610.17 ; 11360,7744.27 14210,7744.27 ; 11300,6983 ccw(c11343,6983) 11343,6940 14227,6940 ccw(c14227,6983) 14270,6983 14270,7897 ccw(c14227,7897) 14227,7940 11343,7940 ccw(c11343,7897) 11300,7897 11300,6983
  text "Layer Stack Up Detail for: PMP9648 REVA.PcbDoc" at 11360,7796.83 h61
  text "Layer" at 11360,7694.27 h31
  text "Gerber" at 12366.76,7694.27 h31
  text "Copper" at 12960.93,7694.27 h31
  text "Dielectric" at 13605.71,7694.27 h31
  text "Name" at 11360,7632.27 h31
  text "Document" at 12366.76,7632.27 h31
  text "Thickness" at 12960.93,7632.27 h31
  text "Material" at 13605.71,7632.27 h31
  text "Top Solder Mask" at 11360,7512.92 h43
  text "(.GTS)" at 12366.76,7512.92 h43
  text "Solder Resist" at 13605.71,7512.92 h43
  text "Top Layer" at 11360,7387.92 h43
  text "(.GTL)" at 12366.76,7387.92 h43
  text "2.8mil" at 12960.93,7387.92 h43
  text "FR-4" at 13605.71,7325.42 h43
  text "Bottom Layer" at 11360,7262.92 h43
  text "(.GBL)" at 12366.76,7262.92 h43
  text "2.8mil" at 12960.93,7262.92 h43
  text "Bottom Solder Mask" at 11360,7137.92 h43
  text "(.GBS)" at 12366.76,7137.92 h43
  text "Solder Resist" at 13605.71,7137.92 h43
  text ".Layer_Name" at 577,-858.49 h60
M13 Component Bodies Top:
  text ".Layer_Name" at 577,-858.49 h60
M14 Component Bodies Bottom:
  text ".Layer_Name" at 577,-858.49 h60
M15 Courtyards Top:
  text ".Layer_Name" at 577,-858.49 h60
M16 Courtyards Bottom:
  text ".Layer_Name" at 577,-858.49 h60
Drill Drawing:
  text ".legend" at 5122.5,725.5 h60
  text "Drill Table" at 5147.5,540.5 h60
  text ".Layer_Name" at 577,-858.49 h60

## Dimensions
0,0 to 3200,0 on M2 Board Dimensions
0,0 to 0,1500 on M2 Board Dimensions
